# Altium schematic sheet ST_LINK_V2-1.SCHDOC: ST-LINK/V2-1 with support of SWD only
size A4; Date: 01-DEC-2013; Author: A.B; CompanyName: STMicroelectronics; Organization: Microcontrollers Division; Address1: 12, Rue Jules HOROWITZ; Address2: 38019 Grenoble; Address3: FRANCE; DocumentNumber: MB1184; Revision: C-01; SheetNumber: 2; SheetTotal: 10; Project: STM32L476G-DISCO
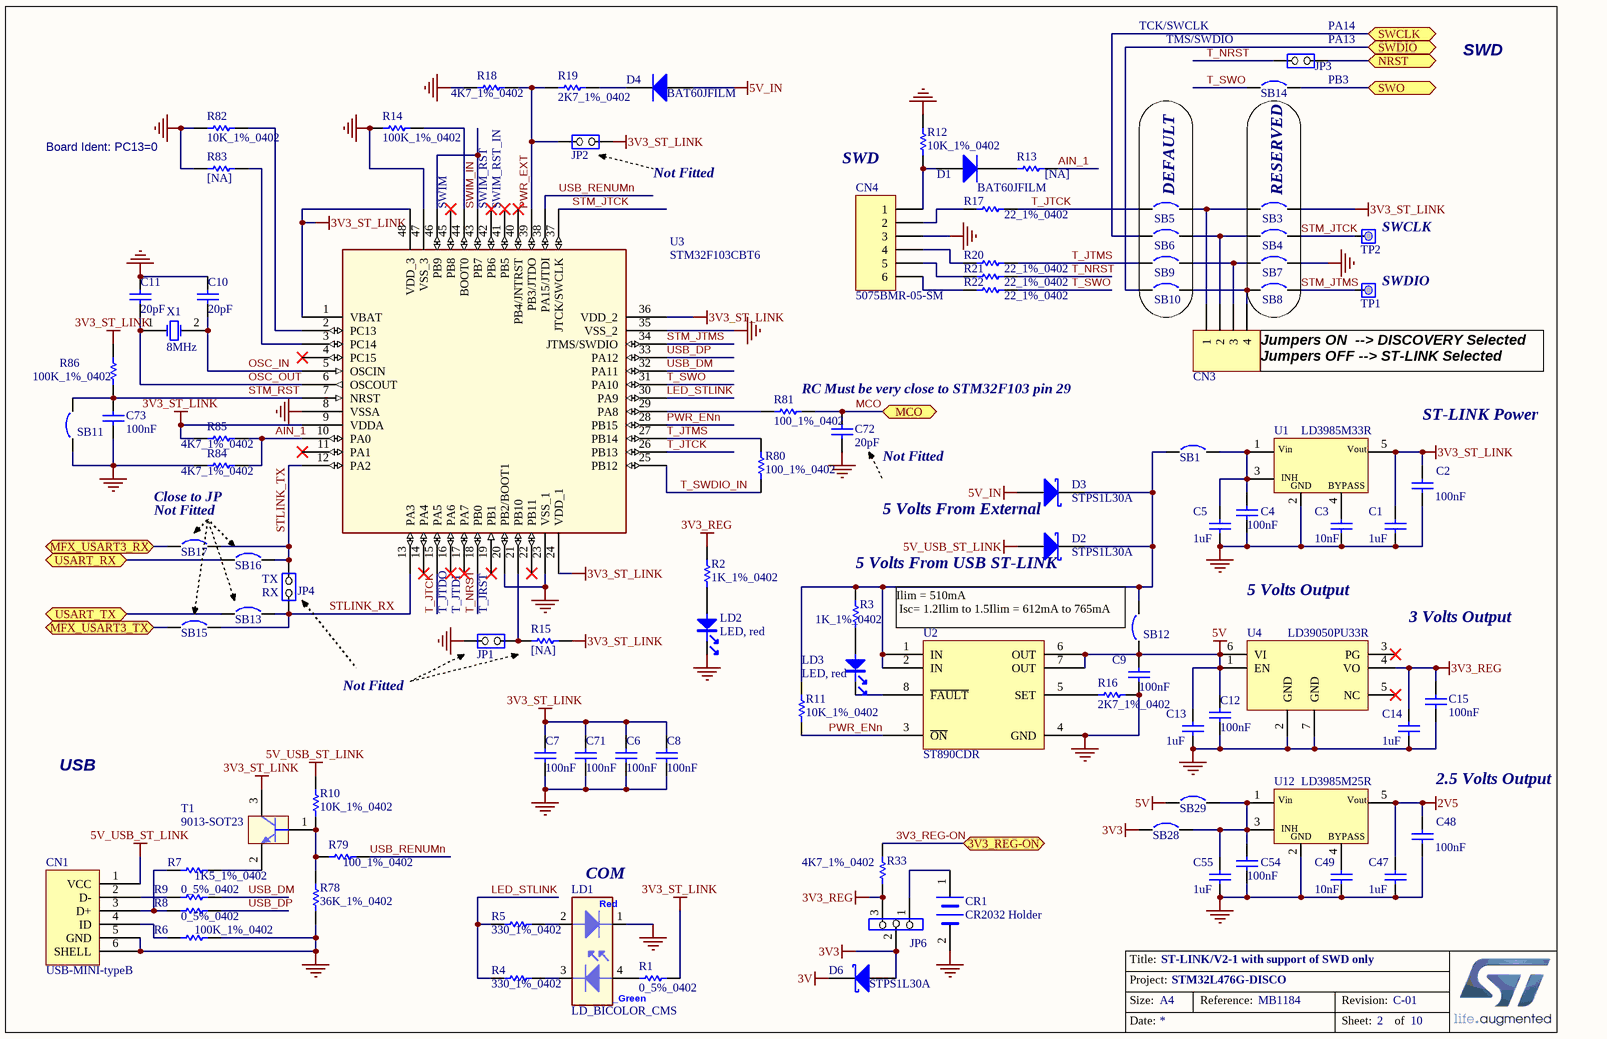
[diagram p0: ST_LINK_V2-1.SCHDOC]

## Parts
C1  1uF  [0603C]
C2  100nF  [0402C]
C3  10nF  [0603C]
C4  100nF  [0402C]
C5  1uF  [0603C]
C6  100nF  [0402C]
C7  100nF  [0402C]
C8  100nF  [0402C]
C9  100nF  [0402C]
C10  20pF  [0402C]
C11  20pF  [0402C]
C12  100nF  [0402C]
C13  1uF  [0603C]
C14  1uF  [0603C]
C15  100nF  [0402C]
C47  1uF  [0603C]
C48  100nF  [0402C]
C49  10nF  [0603C]
C54  100nF  [0402C]
C55  1uF  [0603C]
C71  100nF  [0402C]
C72  20pF  [0402C]
C73  100nF  [0402C]
CN1  USB-MINI-typeB  [USB-MINI-B-SMD]
CN3  Header 4  [Header 4]  (value not drawn)
CN4  5075BMR-05-SM  [HDR1X6]
CR1  CR2032 Holder  [CR2032/SMT]
D1  BAT60JFILM  [SOD323/A]
D2  STPS1L30A  [SMA]
D3  STPS1L30A  [SMA]
D4  BAT60JFILM  [SOD323/A]
D6  STPS1L30A  [SMA]
JP1  Jumper 2 pins  [SIP2/2.54]  (value not drawn)
JP2  Jumper 2 pins  [SIP2/2.54]  (value not drawn)
JP3  Jumper 2 pins  [SIP2/2.54]  (value not drawn)
JP4  Jumper 2 pins  [SIP2/2.54]  (value not drawn)
JP6  Jumper 3 pins  [SIP3]  (value not drawn)
LD1  LD_BICOLOR_CMS  [HSMF-A201]
LD2  LED, red  [0603D]
LD3  LED, red  [0603D]
R1  0_5%_0402  [0402R]
R2  1K_1%_0402  [0402R]
R3  1K_1%_0402  [0402R]
R4  330_1%_0402  [0402R]
R5  330_1%_0402  [0402R]
R6  100K_1%_0402  [0402R]
R7  1K5_1%_0402  [0402R]
R8  0_5%_0402  [0402R]
R9  0_5%_0402  [0402R]
R10  10K_1%_0402  [0402R]
R11  10K_1%_0402  [0402R]
R12  10K_1%_0402  [0402R]
R13  [NA]  [0402R]
R14  100K_1%_0402  [0402R]
R15  [NA]  [0402R]
R16  2K7_1%_0402  [0402R]
R17  22_1%_0402  [0402R]
R18  4K7_1%_0402  [0402R]
R19  2K7_1%_0402  [0402R]
R20  22_1%_0402  [0402R]
R21  22_1%_0402  [0402R]
R22  22_1%_0402  [0402R]
R33  4K7_1%_0402  [0402R]
R78  36K_1%_0402  [0402R]
R79  100_1%_0402  [0402R]
R80  100_1%_0402  [0402R]
R81  100_1%_0402  [0402R]
R82  10K_1%_0402  [0402R]
R83  [NA]  [0402R]
R84  4K7_1%_0402  [0402R]
R85  4K7_1%_0402  [0402R]
R86  100K_1%_0402  [0402R]
SB1  Circuit Breaker  [JP2_SMD]  (value not drawn)
SB3  Circuit Breaker  [JP2_SMD]  (value not drawn)
SB4  Circuit Breaker  [JP2_SMD]  (value not drawn)
SB5  Circuit Breaker  [JP2_SMD]  (value not drawn)
SB6  Circuit Breaker  [JP2_SMD]  (value not drawn)
SB7  Circuit Breaker  [JP2_SMD]  (value not drawn)
SB8  Circuit Breaker  [JP2_SMD]  (value not drawn)
SB9  Circuit Breaker  [JP2_SMD]  (value not drawn)
SB10  Circuit Breaker  [JP2_SMD]  (value not drawn)
SB11  Circuit Breaker  [JP2_SMD]  (value not drawn)
SB12  Circuit Breaker  [JP2_SMD]  (value not drawn)
SB13  Circuit Breaker  [JP2_SMD]  (value not drawn)
SB14  Circuit Breaker  [JP2_SMD]  (value not drawn)
SB15  Circuit Breaker  [JP2_SMD]  (value not drawn)
SB16  Circuit Breaker  [JP2_SMD]  (value not drawn)
SB17  Circuit Breaker  [JP2_SMD]  (value not drawn)
SB28  Circuit Breaker  [JP2_SMD]  (value not drawn)
SB29  Circuit Breaker  [JP2_SMD]  (value not drawn)
T1  9013-SOT23  [SOT23]
TP1  Test point 1 pin with hole  [SIP1/2.54]  (value not drawn)
TP2  Test point 1 pin with hole  [SIP1/2.54]  (value not drawn)
U1  LD3985M33R  [SOT-23-5L]
U2  ST890CDR  [SO-8]
U3  STM32F103CBT6  [QFP48 7x7]
U4  LD39050PU33R  [DFN6_3x3]
U12  LD3985M25R  [SOT-23-5L]
X1  8MHz  [XTAL1]

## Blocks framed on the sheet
DEFAULT: SB5 SB6 SB9 SB10
RESERVED: SB3 SB4 SB7 SB8

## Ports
3V3_REG-ON, MCO, MFX_USART3_RX, MFX_USART3_TX, NRST, SWCLK, SWDIO, SWO, USART_RX, USART_TX

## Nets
2V5: C47.1 C48.2 U12.5(Vout)
3V: D6.2(K)
3V3: D6.1(A) JP6.2 SB28.1
3V3_REG: C14.2 C15.2 JP6.3 R2.2 R33.1 U4.4(VO)
3V3_ST_LINK: C1.1 C2.2 C6.1 C7.2 C8.2 C71.2 JP2.2(NO) R1.2 R15.2 R85.1 R86.2 SB3.2 T1.3(C) U1.5(Vout) U3.1(VBAT) U3.9(VDDA) U3.24(VDD_1) U3.36(VDD_2) U3.48(VDD_3)
5V: C9.2 C12.2 C13.2 SB12.1 SB29.1 U2.6(OUT) U2.7(OUT) U4.1(EN) U4.6(VI)
5V_IN: D3.1(A) D4.1(A)
5V_USB_ST_LINK: CN1.1(VCC) D2.1(A) R10.2
GND: C1.2 C2.1 C3.1 C4.1 C5.1 C6.2 C7.1 C8.1 C9.1 C10.1 C11.1 C12.1 C13.1 C14.1 C15.1 C47.2 C48.1 C49.1 C54.1 C55.1 C71.1 C72.2 C73.1 CN1.5(GND) CN1.6(SHELL) CN4.3 CR1.2(-) JP1.1(COMMON) LD1.1 LD2.2 R6.2 R12.2 R14.1 R16.2 R18.1 R78.1 R82.1 R83.1 R84.1 SB7.2 SB11.1 U1.2(GND) U2.4(GND) U3.8(VSSA) U3.20(PB2/BOOT1) U3.23(VSS_1) U3.35(VSS_2) U3.47(VSS_3) U4.2(GND) U4.7(GND) U12.2(GND)
3V3_REG-ON: R33.2 ; port 3V3_REG-ON
AIN_1: R13.2 R84.2 R85.2 U3.10(PA0)
LED_STLINK: R4.1 R5.1 U3.30(PA9)
MCO: C72.1 R81.2 ; port MCO
MFX_USART3_RX: SB17.1 ; port MFX_USART3_RX
MFX_USART3_TX: SB15.1 ; port MFX_USART3_TX
NRST: JP3.2(NO) ; port NRST
OSC_IN: C10.2 U3.5(OSCIN) X1.2(OSC2)
OSC_OUT: C11.2 U3.6(OSCOUT) X1.1(OSC1)
PWR_ENn: R11.1 U2.3(~{ON}) U3.28(PB15)
PWR_EXT: JP2.1(COMMON) R18.2 R19.1 U3.39(PB3/JTDO)
STLINK_RX: JP4.1(COMMON) SB13.2 SB15.2 U3.13(PA3)
STLINK_TX: JP4.2(NO) SB16.2 SB17.2 U3.12(PA2)
STM_JTCK: SB4.2 TP2.1(COMMON) U3.37(JTCK/SWCLK)
STM_JTMS: SB8.2 TP1.1(COMMON) U3.34(JTMS/SWDIO)
STM_RST: C73.2 R86.1 SB11.2 U3.7(NRST)
SWCLK: SB6.1 ; port SWCLK
SWDIO: SB10.1 ; port SWDIO
SWIM_IN: U3.43(PB7) U3.46(PB9)
SWO: SB14.2 ; port SWO
T_JTCK: R17.2 SB5.1 U3.15(PA5) U3.26(PB13)
T_JTMS: R20.2 R80.2 SB9.1 U3.27(PB14)
T_NRST: JP3.1(COMMON) R21.2 U3.18(PB0)
T_SWDIO_IN: R80.1 U3.25(PB12)
T_SWO: R22.2 SB14.1 U3.31(PA10)
USART_RX: SB16.1 ; port USART_RX
USART_TX: SB13.1 ; port USART_TX
USB_DM: R9.2 U3.32(PA11)
USB_DP: R8.2 U3.33(PA12)
USB_RENUMn: R79.2 U3.38(PA15/JTDI)
NetC3_2: C3.2 U1.4(BYPASS)
NetC4_2: C4.2 C5.2 SB1.2 U1.1(Vin) U1.3(CE)
NetC49_2: C49.2 U12.4(BYPASS)
NetC54_2: C54.2 C55.2 SB28.2 SB29.2 U12.1(Vin) U12.3(CE)
NetCN1_2: CN1.2(D-) R9.1
NetCN1_3: CN1.3(D+) R7.1 R8.1
NetCN1_4: CN1.4(ID) R6.1
NetCN3_1: CN3.1 SB3.1 SB5.2
NetCN3_2: CN3.2 SB4.1 SB6.2
NetCN3_3: CN3.3 SB7.1 SB9.2
NetCN3_4: CN3.4 SB8.1 SB10.2
NetCN4_1: CN4.1 D1.1(A) R12.1
NetCN4_2: CN4.2 R17.1
NetCN4_4: CN4.4 R20.1
NetCN4_5: CN4.5 R21.1
NetCN4_6: CN4.6 R22.1
NetCR1_1: CR1.1(+) JP6.1
NetD1_2: D1.2(K) R13.1
NetD2_2: D2.2(K) D3.2(K) R3.2 R11.2 SB1.1 SB12.2 U2.1(IN) U2.2(IN)
NetD4_2: D4.2(K) R19.2
NetJP1_2: JP1.2(NO) R15.1 U3.21(PB10)
NetLD1_2: LD1.2 R5.2
NetLD1_3: LD1.3 R4.2
NetLD1_4: LD1.4 R1.1
NetLD2_1: LD2.1 R2.1
NetLD3_1: LD3.1 R3.1
NetLD3_2: LD3.2 U2.8(~{FAULT})
NetR7_2: R7.2 T1.2(E)
NetR10_1: R10.1 R78.2 R79.1 T1.1(B)
NetR14_2: R14.2 U3.44(BOOT0)
NetR16_1: R16.1 U2.5(SET)
NetR81_1: R81.1 U3.29(PA8)
NetR82_2: R82.2 U3.2(PC13)
NetR83_2: R83.2 U3.3(PC14)

Not connected (* = marked no-connect by the designer): U3 4(PC15)* 11(PA1)* 14(PA4)* 16(PA6)* 17(PA7)* 19(PB1)* 22(PB11)* 40(PB4/JNTRST)* 41(PB5)* 42(PB6)* 45(PB8)*; U4 3(PG)* 5(NC)*

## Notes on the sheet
- TCK/SWCLK
- TMS/SWDIO
- (near JP3) PA14
- (near JP3) PA13
- PB3
- SWD
- Board Ident: PC13=0
- Not Fitted
- SWIM
- (near U3) SWIM_RST
- SWIM_RST_IN
- (near TP2) SWCLK
- (near TP1) SWDIO
- (near CN3) Jumpers ON  --> DISCOVERY Selected
  Jumpers OFF --> ST-LINK Selected
- (near R81) RC Must be very close to STM32F103 pin 29
- ST-LINK Power
- Close to JP
- (near C72) Not Fitted
- (near D3) 5 Volts From External
- TX
- (near D2) 5 Volts From USB ST-LINK
- RX
- T_JTDO
- T_JTDI
- T_JRST
- (near SB12) Ilim = 510mA
  Isc= 1.2Ilim to 1.5Ilim = 612mA to 765mA
- 5 Volts Output
- 3 Volts Output
- USB
- 2.5 Volts Output
- (near LD1) COM

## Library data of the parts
C1 C5 C13 C14 C47 C55 = Cap_1uF_X5R_10%_0603: Capacitor,1uF,16V,X5R,10%,0603,YAGEO; Manuf_Part_1: CC0603KRX5R7BB105
C2 C4 C6-C9 C12 C15 C48 C54 C71 C73 = Cap_100nF_X7R_10%_0402: Capacitor,100nF,16V,X7R,10%,0402,YAGEO; Manuf_Part_1: CC0402KRX7R7BB104
C3 C49 = Cap_10nF_X7R_10%_0603: Capacitor,10nF,50V,X7R,10%,0603,YAGEO; Manuf_Part_1: CC0603KRX7R9BB103
C10 C11 = Cap_20pF_NPO_5%_0402: Capacitor,20pF,50V,NPO,5%,0402,YAGEO; Order: CC0402JRNPO9BN200
C72 = Cap_20pF_NPO_5%_0402: Capacitor,20pF,50V,NPO,5%,0402,YAGEO; Order: CC0402JRNPO9BN200; Fitted: NO
CN1 = USB-MINI-typeB connector: Manuf_Part_1: 5075BMR-05-SM; Manuf_Part_2: 218205M1110T; Manuf_2: lyconn
CN3 = Header 4: Header, 4-Pin
CN4 = Header 6: Header, 6-Pin
CR1 = BATT_2032: CR2032 socket, S8421-45R; Manuf_2: Lotes; Manuf_Part_2: KB7410AP2L; Manuf_1: HARWIN; Order: 952-1737-2-ND; ECCN_US/EU: EAR99/NEC
D1 D4 = BAT60JFILM: Manuf_1: STM; Provided: ST; ECCN_US/EU: EAR99/NEC; Ref St: 9151097
D2 D3 D6 = STPS1L30A: Low Drop power Schottky rectifier; Manuf_1: STM; Provided: ST; Ref St: xxxxxxxx; ECCN_US/EU: EAR99/NEC
JP1 JP2 JP4 = Jumper2: Fitted: NO
JP3 = Jumper2
JP6 = Jumper3
LD1 = LD_BICOLOR_CMS: Bicolor Led; Manuf_Part_1: HSMF-A201-A00J1; Manuf_1: Avago Technologies; Manuf_2: everluck; Manuf_Part_2: LE-RGW35280; Ref St: xxxxxx; ECCN_US/EU: EAR99/NEC
LD2 LD3 = LED_red: LED, red, 0603; Manuf_1: everlight; Manuf_Part_1: 19-213-R6C-AP1Q2B/3T; ECCN_US/EU: EAR99/NEC
R1 R8 R9 = Res_0_5%_0402: Resistor,0,0402,5%,YAGEO; Manuf_Part_1: RC0402JR-070RL; Value: 0; Order: 2363467
R2 R3 = Res_1K_1%_0402: Resistor,1K,0402,1%,YAGEO; Manuf_Part_1: RC0402FR-071KL
R4 R5 = Res_330_1%_0402: Resistor,330,0402,1%,YAGEO; Manuf_Part_1: RC0402FR-07330RL; Value: 330
R6 R14 R86 = Res_100K_1%_0402: Resistor,100K,0402,1%,YAGEO; Manuf_Part_1: RT0402FRE07100KL
R7 = Res_1K5_1%_0402: Resistor,1K5,0402,1%,YAGEO; Manuf_Part_1: RC0402FR-071K5L
R10-R12 R82 = Res_10K_1%_0402: Resistor,10K,0402,1%,YAGEO; Manuf_Part_1: RC0402FR-0710KL
R13 R15 R83 = Res_NA_0402: Resistor,[NA],0402; Fitted: NO
R16 R19 = Res_2K7_1%_0402: Resistor,2K7,0402,1%,YAGEO; Manuf_Part_1: RC0402FR-072K7L
R17 R20-R22 = Res_22_1%_0402: Resistor,22,0402,1%,YAGEO; Manuf_Part_1: RC0402FR-0722RL; Value: 22
R18 R33 R84 R85 = Res_4K7_1%_0402: Resistor,4K7,0402,1%,YAGEO; Manuf_Part_1: RT0402FRE074K7L
R78 = Res_36K_1%_0402: Resistor,36K,0402,1%,YAGEO; Manuf_Part_1: RC0402FR-0736KL
R79-R81 = Res_100_1%_0402: Resistor,100,0402,1%,YAGEO; Manuf_Part_1: RC0402FR-07100RL; Value: 100; Order: 9239111
SB1 SB5 SB6 SB9 SB10 SB13 SB16 SB28 = Circuit Breaker: Solder: YES
SB3 SB4 SB7 SB8 SB11 SB12 SB14 SB15 SB17 SB29 = Circuit Breaker: Solder: NO
T1 = 9013-SOT23: NPN Bipolar Transistor; Manuf_1: NXP; Manuf_Part_1: BSR14; Order: 1081310; ECCN_US/EU: EAR99/NEC
TP1 TP2 = TP1: Test Point; Fitted: NO
U1 = LD3985M33R: Ultra low drop-low noise BiCMOS voltage, regulators low ESR capacitors compatible; Manuf_1: STM; Provided: ST; Ref St: 9176161; ECCN_US/EU: EAR99/NEC
U2 = ST890CDR: 1.2 A current limited high-side power switch with thermal shutdown; Manuf_1: STM; ECCN_US/EU: EAR99/NEC; Provided: ST
U3 = STM32F103CBT6: Medium-density performance line ARM-based 32-bit MCU with 128KB Flash; Manuf_1: STM; Ref St: xxxxxxxx; Provided: ST; ECCN_US/EU: 3A991A2/NEC
U4 = LD39050P: Ultra low drop-low , 500 mA low quiescent current; Manuf_1: STM; Provided: ST; ECCN_US/EU: EAR99/NEC; Ref St: xxxxxxxx
U12 = LD3985M25R: Ultra low drop-low noise BiCMOS voltage, regulators low ESR capacitors compatible; Manuf_1: STM; Provided: ST; Ref St: 9176007; ECCN_US/EU: EAR99/NEC
X1 = XTAL_8MHZ_20PPM: Crystal Oscillator,8Mhz,20PF,20PPM,-10-70 degree,DIP,HC-49S; Manuf_Part_1: HC-49S-C20QSA-8.000MHZ; ECCN_US/EU: EAR99/NEC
